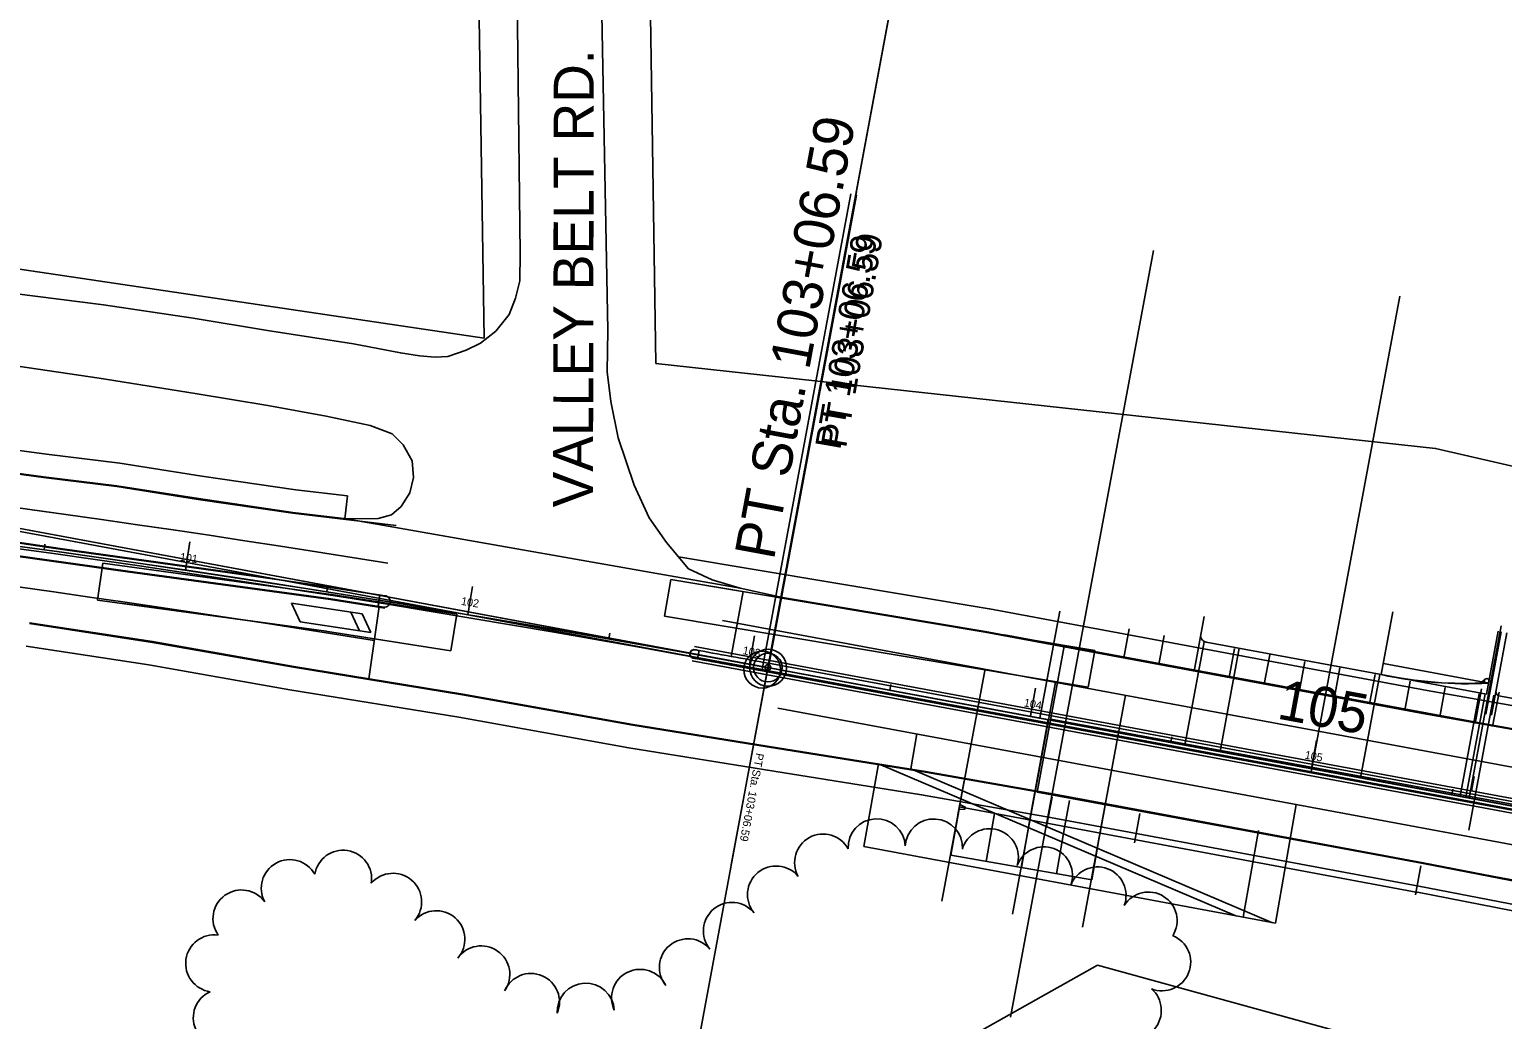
# Model space of a CAD drawing. Extents: x -25029 to 2274964, y -81170 to 687028.
# Drawn here: x -6912 to -6397, y -66270 to -65924 of the extents above; entities that cross this region are included whole.
import ezdxf

# ---------------------------------------------------------------- set-up
doc = ezdxf.new("R2010")
doc.units = 0
for name, color, linetype in [('81911BEA - RW_X_Fee_RW', 7, 'Continuous'), ('AP_X_Lights', 7, 'Continuous'), ('AP_X_Markings', 7, 'Continuous'), ('BD_X_Canopy', 7, 'Continuous'), ('GE_X_CL_100', 7, 'Continuous'), ('GE_X_CL_20', 7, 'Continuous'), ('GK_Visualization', 7, 'Continuous'), ('MT_P_Edge_Line', 7, 'Continuous'), ('MT_P_Lane_Line', 7, 'Continuous'), ('PM_P_Stop_Line', 7, 'Continuous'), ('PV_X_EOP', 7, 'Continuous'), ('PV_X_Steps', 7, 'Continuous'), ('RD_P_Gate', 7, 'Continuous'), ('RD_X_Bedrock', 7, 'Continuous'), ('RD_X_Bumper_Block', 7, 'Continuous'), ('RD_X_GR_Rt', 7, 'Continuous'), ('SC_Scratch18', 7, 'Continuous'), ('SC_Scratch19', 7, 'Continuous'), ('SG_X_Detection', 7, 'Continuous'), ('TREES', 7, 'Continuous')]:
    doc.layers.add(name, color=color, linetype=linetype)

msp = doc.modelspace()

# ---------------------------------------------------------------- linework, layer by layer
at = {"layer": '81911BEA - RW_X_Fee_RW'}
for p, q in [((-6753.44, -66031.98), (-6761.67, -65499.78)), ((-7043.13, -65989.15), (-6753.44, -66031.98)), ((-6538.81, -66251.32), (-6650.06, -66313.81))]:
    msp.add_line(p, q, dxfattribs=at)
for points in [[(-6701.67, -65498.85), (-6700.35, -65584.74), (-6693.3, -66040.87)], [(-6693.3, -66040.87), (-6420.54, -66070.56), (-6385.59, -66078.68)], [(-6538.81, -66251.32), (-6456.29, -66274.14), (-6455.65, -66274.32)]]:
    msp.add_lwpolyline(points, dxfattribs=at)
at = {"layer": 'AP_X_Lights'}
msp.add_lwpolyline([(-6913.64, -66139.8), (-6870.76, -66146.32), (-6821.42, -66155.02), (-6762.28, -66164.63), (-6702.72, -66175.29), (-6652.06, -66183.48), (-6600.36, -66191.74), (-6555.27, -66199.64), (-6426.35, -66223.67)], dxfattribs=at)
at = {"layer": 'AP_X_Markings'}
msp.add_line((-6433.03, -66017.35), (-6464.02, -66183.75), dxfattribs=at)
at = {"layer": 'BD_X_Canopy'}
for q in [(-6591.54, -65810.29), (-7120.12, -66060.66), (-7701.63, -71785.78), (-6654.13, -66147.23)]:
    msp.add_line((-6654.13, -66147.23), q, dxfattribs=at)
at = {"layer": 'GE_X_CL_100'}
for p, q in [((-6653.22, -66142.32), (-6611.28, -65916.59)), ((-6857.88, -66113.16), (-6856.41, -66103.27)), ((-6759.1, -66128.74), (-6757.46, -66118.87)), ((-6660.61, -66146.03), (-6658.8, -66136.2)), ((-6654.13, -66147.23), (-6013.27, -66266.31)), ((-6562.29, -66164.3), (-6560.47, -66154.46)), ((-6463.98, -66182.57), (-6462.15, -66172.73))]:
    msp.add_line(p, q, dxfattribs=at)
msp.add_circle((-6654.13, -66147.23), 5, dxfattribs=at)
msp.add_arc((-7701.63, -71785.78), 5735.02, 79.475877, 88.9247, dxfattribs=at)
at = {"layer": 'GE_X_CL_20'}
for p, q in [((-6656.12, -66147.95), (-6625.14, -65981.55)), ((-7122.08, -66061.19), (-5080.45, -66441.35)), ((-6907.37, -66106.02), (-6907.09, -66104.04)), ((-6857.88, -66113.16), (-6857.59, -66111.19)), ((-6808.46, -66120.74), (-6808.15, -66118.76)), ((-6759.1, -66128.74), (-6758.77, -66126.76)), ((-6709.82, -66137.17), (-6709.47, -66135.2)), ((-6660.61, -66146.03), (-6660.25, -66144.06)), ((-6654.31, -66148.21), (-6666.96, -66216.27)), ((-6611.45, -66155.16), (-6611.09, -66153.2)), ((-6562.29, -66164.3), (-6561.93, -66162.33)), ((-6513.13, -66173.43), (-6512.77, -66171.46)), ((-6463.98, -66182.57), (-6463.61, -66180.6)), ((-6414.82, -66191.7), (-6414.45, -66189.73))]:
    msp.add_line(p, q, dxfattribs=at)
for centre, radius in [((-6656.12, -66147.95), 6.46), ((-6654.13, -66147.23), 1)]:
    msp.add_circle(centre, radius, dxfattribs=at)
msp.add_arc((-7704.96, -71780.77), 5729.63, 79.452222, 88.91, dxfattribs=at)
at = {"layer": 'GK_Visualization'}
for p, q in [((-6654.05, -66147.23), (-6654.21, -66147.23)), ((-6654.2, -66147.3), (-6654.06, -66147.16)), ((-6654.2, -66147.16), (-6654.06, -66147.3)), ((-6654.13, -66147.15), (-6654.13, -66147.31)), ((-6654.13, -66147.23), (-6028.02, -66263.57))]:
    msp.add_line(p, q, dxfattribs=at)
msp.add_arc((-7701.63, -71785.78), 5735.02, 79.475877, 88.9247, dxfattribs=at)
msp.add_arc((-7701.63, -71785.78), 5735.02, 79.475877, 88.9247, dxfattribs=at)
at = {"layer": 'MT_P_Edge_Line'}
for p, q in [((-6907.58, -66080.78), (-6935.5, -66077.06)), ((-6881.95, -66083.9), (-6907.57, -66080.78)), ((-6853.42, -66088.4), (-6881.96, -66083.9)), ((-6820.35, -66093.2), (-6853.42, -66088.4)), ((-6784.17, -66097.59), (-6820.34, -66093.2)), ((-6949.04, -66098.69), (-6900.89, -66105.76)), ((-6878.16, -66113.72), (-6937.06, -66105.59)), ((-6900.89, -66105.76), (-6842.34, -66113.89)), ((-6807.11, -66123.43), (-6878.16, -66113.72)), ((-6842.34, -66113.89), (-6787.49, -66122.32)), ((-6578.13, -66134.83), (-6676.21, -66118.4)), ((-6788.2, -66126.41), (-6807.11, -66123.43)), ((-6912.48, -66131.63), (-6869.43, -66138.18)), ((-6869.42, -66138.18), (-6820.04, -66146.89)), ((-6424.95, -66163.37), (-6578.13, -66134.83)), ((-6679.82, -66139.92), (-6154.55, -66237.52)), ((-6820.04, -66146.89), (-6760.89, -66156.5)), ((-6680.67, -66144.84), (-6155.34, -66242.46)), ((-6760.89, -66156.5), (-6701.33, -66167.16)), ((-6337.4, -66178.86), (-6424.95, -66163.37)), ((-6701.33, -66167.16), (-6650.75, -66175.34)), ((-6650.76, -66175.34), (-6599, -66183.6)), ((-6598.99, -66183.6), (-6553.8, -66191.52)), ((-6553.8, -66191.52), (-6424.84, -66215.56)), ((-6424.84, -66215.56), (-6386.28, -66223.01))]:
    msp.add_line(p, q, dxfattribs=at)
for points in [[(-6789.9, -66121.86), (-6790.53, -66125.79), (-6788.69, -66126.08), (-6788.11, -66126.13), (-6787.66, -66126.04), (-6787.22, -66125.84), (-6786.86, -66125.56), (-6786.64, -66125.3), (-6786.43, -66124.93), (-6786.32, -66124.57), (-6786.27, -66124.1), (-6786.29, -66123.82), (-6786.38, -66123.48), (-6786.61, -66123.02), (-6786.9, -66122.68), (-6787.36, -66122.35), (-6787.73, -66122.21), (-6788.1, -66122.14), (-6788.8, -66122.03)], [(-6678.17, -66141.3), (-6678.72, -66144.24), (-6680.33, -66143.95), (-6680.75, -66143.76), (-6681.1, -66143.43), (-6681.36, -66142.93), (-6681.42, -66142.42), (-6681.28, -66141.86), (-6680.86, -66141.33), (-6680.12, -66141.01), (-6679.21, -66141.1), (-6678.47, -66141.24)]]:
    msp.add_lwpolyline(points, close=True, dxfattribs=at)
at = {"layer": 'MT_P_Lane_Line'}
msp.add_line((-6670.04, -66130.77), (-5796.86, -66293.03), dxfattribs=at)
msp.add_lwpolyline([(-6650.64, -66161.42), (-6015.7, -66279.4), (-5892.65, -66302.28), (-5892.6, -66302.03), (-5802.39, -66318.76)], dxfattribs=at)
for radius, start in [(5748.29, 80.845144), (5720.86, 80.84919)]:
    msp.add_arc((-7701.63, -71785.78), radius, start, 88.9247, dxfattribs=at)
at = {"layer": 'PM_P_Stop_Line'}
for p, q in [((-6654.05, -66147.29), (-6623.1, -65980.88)), ((-7120.03, -66060.65), (-5078.3, -66440.28)), ((-6666.94, -66143.34), (-6662.81, -66120.65)), ((-6793.78, -66151.16), (-6790.1, -66125.86))]:
    msp.add_line(p, q, dxfattribs=at)
msp.add_circle((-6654.05, -66147.29), 6.46, dxfattribs=at)
msp.add_arc((-7701.44, -71780.38), 5729.63, 79.466922, 88.9247, dxfattribs=at)
at = {"layer": 'PV_X_EOP'}
for p, q in [((-6710.1, -66029.2), (-6712.8, -65890.7)), ((-6710.39, -66043.75), (-6710.1, -66029.2)), ((-6923.81, -66040.73), (-6888.08, -66046)), ((-6888.08, -66046), (-6854.52, -66051.38)), ((-6709.07, -66054.21), (-6710.39, -66043.75)), ((-6854.52, -66051.38), (-6829.06, -66055.54)), ((-6829.06, -66055.54), (-6808.63, -66059.32)), ((-6706.46, -66066.86), (-6709.07, -66054.21)), ((-6808.63, -66059.32), (-6793.23, -66062.57)), ((-6793.23, -66062.57), (-6785.59, -66065.53)), ((-6785.59, -66065.53), (-6781.75, -66069.38)), ((-6700.92, -66083.42), (-6706.46, -66066.86)), ((-6906.53, -66072.6), (-6934.47, -66068.88)), ((-6781.75, -66069.38), (-6778.64, -66074.98)), ((-6907.54, -66080.53), (-6935.46, -66076.81)), ((-6880.82, -66075.73), (-6906.53, -66072.6)), ((-6852.19, -66080.24), (-6880.82, -66075.73)), ((-6778.64, -66074.98), (-6778.06, -66080.8)), ((-6881.92, -66083.65), (-6907.54, -66080.53)), ((-6819.26, -66085.02), (-6852.19, -66080.24)), ((-6778.06, -66080.8), (-6779.43, -66086.16)), ((-6853.38, -66088.15), (-6881.92, -66083.65)), ((-6801.15, -66087.22), (-6819.26, -66085.02)), ((-6802.12, -66095.16), (-6801.15, -66087.22)), ((-6779.43, -66086.16), (-6782.47, -66090.93)), ((-6695.62, -66094.87), (-6700.92, -66083.42)), ((-6820.31, -66092.95), (-6853.38, -66088.15)), ((-6801.59, -66095.22), (-6820.31, -66092.95)), ((-6782.47, -66090.93), (-6785.82, -66093.87)), ((-6790.53, -66095.1), (-6801.59, -66095.22)), ((-6801.59, -66095.22), (-6663.79, -66119.46)), ((-6785.82, -66093.87), (-6790.53, -66095.1)), ((-6689.57, -66103.53), (-6695.62, -66094.87)), ((-6949.07, -66098.93), (-6900.92, -66106)), ((-6878.12, -66113.47), (-6937.02, -66105.34)), ((-6900.92, -66106), (-6842.37, -66114.13)), ((-6681.92, -66112.65), (-6689.57, -66103.53)), ((-6576.76, -66126.69), (-6685.41, -66108.5)), ((-6807.07, -66123.18), (-6878.12, -66113.47)), ((-6673.67, -66116.6), (-6681.92, -66112.65)), ((-6842.37, -66114.13), (-6806.97, -66119.17)), ((-6663.79, -66119.46), (-6673.67, -66116.6)), ((-6788.69, -66126.08), (-6807.07, -66123.18)), ((-6788.11, -66122.14), (-6806.45, -66119.25)), ((-6790.53, -66125.79), (-6789.9, -66121.86)), ((-6649.01, -66122.7), (-6663.79, -66119.46)), ((-6578.08, -66134.58), (-6649.01, -66122.7)), ((-6423.44, -66155.26), (-6576.62, -66126.72)), ((-6912.51, -66131.87), (-6869.46, -66138.42)), ((-6869.46, -66138.42), (-6820.08, -66147.13)), ((-6424.9, -66163.12), (-6578.08, -66134.58)), ((-6913.64, -66139.8), (-6870.76, -66146.32)), ((-6870.76, -66146.32), (-6821.42, -66155.02)), ((-6820.08, -66147.13), (-6760.93, -66156.74)), ((-6654.4, -66148.71), (-6156.72, -66241.19)), ((-6653.86, -66145.76), (-6156.02, -66238.26)), ((-6821.42, -66155.02), (-6762.28, -66164.63)), ((-6760.93, -66156.74), (-6701.37, -66167.4)), ((-6762.28, -66164.63), (-6702.72, -66175.29)), ((-6337.35, -66178.61), (-6424.9, -66163.12)), ((-6701.37, -66167.4), (-6650.79, -66175.58)), ((-6702.72, -66175.29), (-6652.06, -66183.48)), ((-6650.79, -66175.58), (-6599.03, -66183.84)), ((-6652.06, -66183.48), (-6600.36, -66191.74)), ((-6599.03, -66183.84), (-6553.84, -66191.76)), ((-6600.36, -66191.74), (-6555.27, -66199.64)), ((-6553.84, -66191.76), (-6424.88, -66215.8)), ((-6555.27, -66199.64), (-6426.35, -66223.67)), ((-6424.88, -66215.8), (-6386.32, -66223.25))]:
    msp.add_line(p, q, dxfattribs=at)
for points in [[(-6742.39, -65862.73), (-6740.83, -66002.33), (-6740.96, -66011.91), (-6742.41, -66017.97), (-6744.7, -66023.74), (-6749.3, -66029.52), (-6754.64, -66033.82), (-6759.72, -66036.17), (-6766.07, -66038.42), (-6770.55, -66038.68), (-6776.07, -66038.21), (-6782.7, -66037.17), (-6799.08, -66034.03), (-6829.16, -66029.36), (-6855.24, -66025.05), (-6886.57, -66020.35), (-6917.85, -66016.42)], [(-6167.72, -66202.64), (-6208.38, -66195.11), (-6335.91, -66170.75), (-6423.51, -66155.25)], [(-6426.4, -66223.66), (-6387.76, -66231.12), (-6319.31, -66242.94), (-6227.38, -66261.43), (-6149.13, -66275.73)]]:
    msp.add_lwpolyline(points, dxfattribs=at)
for centre, radius, start, end in [((-6788.27, -66124.14), 2, 257.9768, 85.4022), ((-6679.83, -66142.51), 1.56, 96.583, 274.3035), ((-7701.63, -71785.78), 5736.52, 79.475877, 79.741457), ((-7701.63, -71785.78), 5733.52, 79.475877, 79.733029)]:
    msp.add_arc(centre, radius, start, end, dxfattribs=at)
at = {"layer": 'PV_X_Steps'}
for p, q in [((-6886.83, -66110.75), (-6888.68, -66123.62)), ((-6806.87, -66121.68), (-6886.83, -66110.75)), ((-6886.58, -66108.97), (-6886.58, -66108.97)), ((-6690.25, -66129.23), (-6688.11, -66116.41)), ((-6539.7, -66141.27), (-6688.11, -66116.41)), ((-6578.13, -66134.83), (-6676.21, -66118.4)), ((-6808.63, -66134.56), (-6888.68, -66123.62)), ((-6762.97, -66128.6), (-6806.84, -66121.68)), ((-6808.63, -66134.56), (-6879.68, -66124.85)), ((-6762.97, -66128.6), (-6765.1, -66141.42)), ((-6762.89, -66128.11), (-6762.89, -66128.11)), ((-6542.08, -66154.05), (-6690.25, -66129.23)), ((-6765.1, -66141.42), (-6808.86, -66134.52)), ((-6542.08, -66154.05), (-6539.7, -66141.27))]:
    msp.add_line(p, q, dxfattribs=at)
at = {"layer": 'RD_P_Gate'}
for p, q in [((-6558.95, -66164.92), (-6551.99, -66127.5)), ((-6408.82, -66192.81), (-6397.63, -66132.59)), ((-6508.22, -66174.34), (-6501.5, -66138.2)), ((-6495.93, -66176.63), (-6489.21, -66140.49)), ((-6578.15, -66147.74), (-6593.23, -66228.91)), ((-6446.77, -66185.76), (-6440.05, -66149.62)), ((-6568.54, -66233.5), (-6553.46, -66152.33)), ((-6528.99, -66156.87), (-6544.07, -66238.04)), ((-6411.87, -66192.25), (-6405.22, -66156.45)), ((-6409.9, -66192.61), (-6403.19, -66156.47)), ((-6408.89, -66204.12), (-6400.1, -66156.85)), ((-6556.01, -66165.46), (-6562.51, -66200.4)), ((-6602.02, -66170.45), (-6604.17, -66182.69)), ((-6615.45, -66180.97), (-6620.51, -66209.85)), ((-6615.45, -66180.97), (-6490.46, -66234.1)), ((-6604.17, -66182.69), (-6477.58, -66236.5)), ((-6538.16, -66206.22), (-6536.27, -66196.03)), ((-6469.29, -66195.12), (-6476.57, -66236.69)), ((-6482.47, -66204.28), (-6487.79, -66234.6)), ((-6620.51, -66209.85), (-6476.57, -66236.69))]:
    msp.add_line(p, q, dxfattribs=at)
at = {"layer": 'RD_X_Bedrock'}
for p, q in [((-6554.18, -66139.29), (-6551.99, -66127.5)), ((-6529.61, -66143.87), (-6527.72, -66133.69)), ((-6505.03, -66148.45), (-6501.5, -66129.43)), ((-6517.32, -66146.16), (-6515.43, -66135.97)), ((-6492.74, -66150.74), (-6490.85, -66140.54)), ((-6480.45, -66153.03), (-6478.56, -66142.82)), ((-6468.17, -66155.32), (-6466.27, -66145.1)), ((-6455.88, -66157.61), (-6453.98, -66147.39)), ((-6443.59, -66159.9), (-6441.69, -66149.67)), ((-6431.3, -66162.19), (-6429.4, -66151.96)), ((-6419.01, -66164.48), (-6417.11, -66154.24)), ((-6406.72, -66166.77), (-6404.48, -66154.67)), ((-6400.58, -66167.91), (-6398.33, -66155.81)), ((-6587.63, -66198.76), (-6585.42, -66186.89)), ((-6562.51, -66200.4), (-6560.85, -66191.46)), ((-6550.45, -66203.93), (-6548.56, -66193.74)), ((-6538.16, -66206.22), (-6536.27, -66196.03)), ((-6525.87, -66208.5), (-6523.98, -66198.31)), ((-6427.55, -66226.77), (-6425.66, -66216.58))]:
    msp.add_line(p, q, dxfattribs=at)
at = {"layer": 'RD_X_Bumper_Block'}
for p, q in [((-6439.54, -66149.72), (-6435.44, -66127.7)), ((-6402.94, -66163.52), (-6397.59, -66134.73)), ((-6402.67, -66156.59), (-6398.57, -66134.55)), ((-6400.97, -66163.88), (-6395.62, -66135.1)), ((-6439.54, -66149.72), (-6402.67, -66156.59)), ((-6438.8, -66145.79), (-6401.94, -66152.65)), ((-6587.13, -66196.08), (-6590.08, -66212.89)), ((-6574.82, -66198.24), (-6577.76, -66215.04)), ((-6562.51, -66200.4), (-6565.45, -66217.2)), ((-6550.19, -66202.56), (-6553.14, -66219.36)), ((-6537.88, -66204.71), (-6540.83, -66221.52)), ((-6590.08, -66212.89), (-6540.83, -66221.52))]:
    msp.add_line(p, q, dxfattribs=at)
at = {"layer": 'RD_X_GR_Rt'}
for p, q in [((-6439.54, -66149.72), (-6500.75, -66138.31)), ((-6403.13, -66151.28), (-6404.9, -66152.8)), ((-6407.94, -66190.43), (-6406.99, -66185.31)), ((-6587.12, -66195.99), (-6426.76, -66225.88)), ((-6556.59, -66202.79), (-6554.7, -66192.6)), ((-6587.42, -66197.64), (-6587.52, -66198.76))]:
    msp.add_line(p, q, dxfattribs=at)
for points in [[(-6177.38, -66198.31), (-6207.91, -66192.66), (-6335.45, -66168.29), (-6398.52, -66157.13)], [(-6426.83, -66225.87), (-6388.17, -66233.34), (-6319.73, -66245.15), (-6227.81, -66263.64), (-6149.53, -66277.94)]]:
    msp.add_lwpolyline(points, dxfattribs=at)
msp.add_lwpolyline([(-6587.33, -66196.87), (-6587, -66195.14), (-6585.05, -66196.04), (-6585.18, -66196.75)], close=True, dxfattribs=at)
msp.add_circle((-6402.61, -66151.89), 0.803, dxfattribs=at)
for centre, radius, start, end in [((-6500.48, -66136.02), 2.31, 187.3946, 262.739), ((-6410.03, -66014.07), 138.82, 257.7276, 273.3411), ((-6410.03, -66014.07), 138.72, 257.7276, 273.3411), ((-6397.66, -66155.6), 1.75, 173.5103, 240.5717)]:
    msp.add_arc(centre, radius, start, end, dxfattribs=at)
at = {"layer": 'SC_Scratch18'}
for p, q in [((-6623.18, -65981.95), (-6654.16, -66148.35)), ((-6519.25, -66001.3), (-6569.19, -66269.5))]:
    msp.add_line(p, q, dxfattribs=at)
at = {"layer": 'SC_Scratch19'}
for p, q in [((-6571.38, -66135.85), (-6007.69, -66239.94)), ((-6550.46, -66139.71), (-6559.91, -66190.87)), ((-6555.19, -66165.29), (-6050.14, -66258.55)), ((-6559.91, -66190.87), (-6054.87, -66284.13))]:
    msp.add_line(p, q, dxfattribs=at)
at = {"layer": 'SG_X_Detection'}
for p, q in [((-6796.1, -66128.42), (-6820.83, -66124.72)), ((-6817.76, -66131.25), (-6820.83, -66124.72)), ((-6796.98, -66134.35), (-6800.05, -66127.83)), ((-6793.03, -66134.94), (-6796.1, -66128.42)), ((-6817.76, -66131.25), (-6793.03, -66134.94))]:
    msp.add_line(p, q, dxfattribs=at)
at = {"layer": 'TREES'}
for centre, start, end in [((-6616.04, -66210.14), 2.8699, 182.8699), ((-6596.07, -66210.21), 356.7498, 176.7498), ((-6634.79, -66215.47), 28.8518, 208.8518), ((-6576.5, -66213.61), 343.5454, 163.5454), ((-6802.76, -66221.14), 350.9377, 170.9377), ((-6557.54, -66219.95), 339.444, 159.444), ((-6821.38, -66224.41), 28.955, 208.955), ((-6651.26, -66226.66), 39.5501, 219.5501), ((-6785.27, -66229.2), 319.6136, 139.6136), ((-6538.82, -66226.98), 339.444, 159.444), ((-6838.28, -66235.04), 35.4032, 215.4032), ((-6520.96, -66235.77), 328.1283, 148.1283), ((-6666.68, -66239.4), 39.5501, 219.5501), ((-6770.14, -66242.28), 318.6806, 138.6806), ((-6847.83, -66250.74), 81.9684, 261.9684), ((-6682.1, -66252.13), 39.5501, 219.5501), ((-6516.2, -66250.32), 248.0664, 68.0664), ((-6754.43, -66254.61), 325.0553, 145.0553), ((-6698.84, -66262.81), 25.524, 205.524), ((-6737.03, -66264.25), 336.9477, 156.9477), ((-6717.85, -66267.64), 3.0119, 183.0119), ((-6845.17, -66269.78), 113.9507, 293.9507), ((-6526.47, -66267.18), 229.2583, 49.2583)]:
    msp.add_arc(centre, 10, start, end, dxfattribs=at)

# ---------------------------------------------------------------- texts
at = {"layer": 'GE_X_CL_100'}
for s, rotation, p in [('VALLEY BELT RD.', 89.8965, (-6715.31, -66091.23)), ('PT Sta. 103+06.59', 79.4759, (-6652.06, -66109.92)), ('105', 349.4735, (-6476.35, -66165.01))]:
    msp.add_text(s, height=14, rotation=rotation, dxfattribs=at).set_placement(p)
at = {"layer": 'GE_X_CL_20'}
for s, height, rotation, p in [('PT 103+06.59', 8.96, 80.1234, (-6628.83, -66071.31)), ('101', 2.8, 351.5398, (-6860, -66109.82)), ('102', 2.8, 350.5408, (-6761.62, -66125.28)), ('103', 2.8, 349.5417, (-6663.1, -66142.52)), ('104', 2.8, 349.4735, (-6564.73, -66160.79)), ('PT Sta. 103+06.59', 2.8, 259.4759, (-6658.23, -66176.98)), ('105', 2.8, 349.4735, (-6466.45, -66179.05))]:
    msp.add_text(s, height=height, rotation=rotation, dxfattribs=at).set_placement(p)
at = {"layer": 'GK_Visualization'}
msp.add_text('40', height=0.14, dxfattribs=at).set_placement((-6654.13, -66147.23))
at = {"layer": 'PM_P_Stop_Line'}
msp.add_text('PT 103+06.59', height=8.96, rotation=80.1381, dxfattribs=at).set_placement((-6626.78, -66070.64))

doc.saveas('drawing.dxf')
